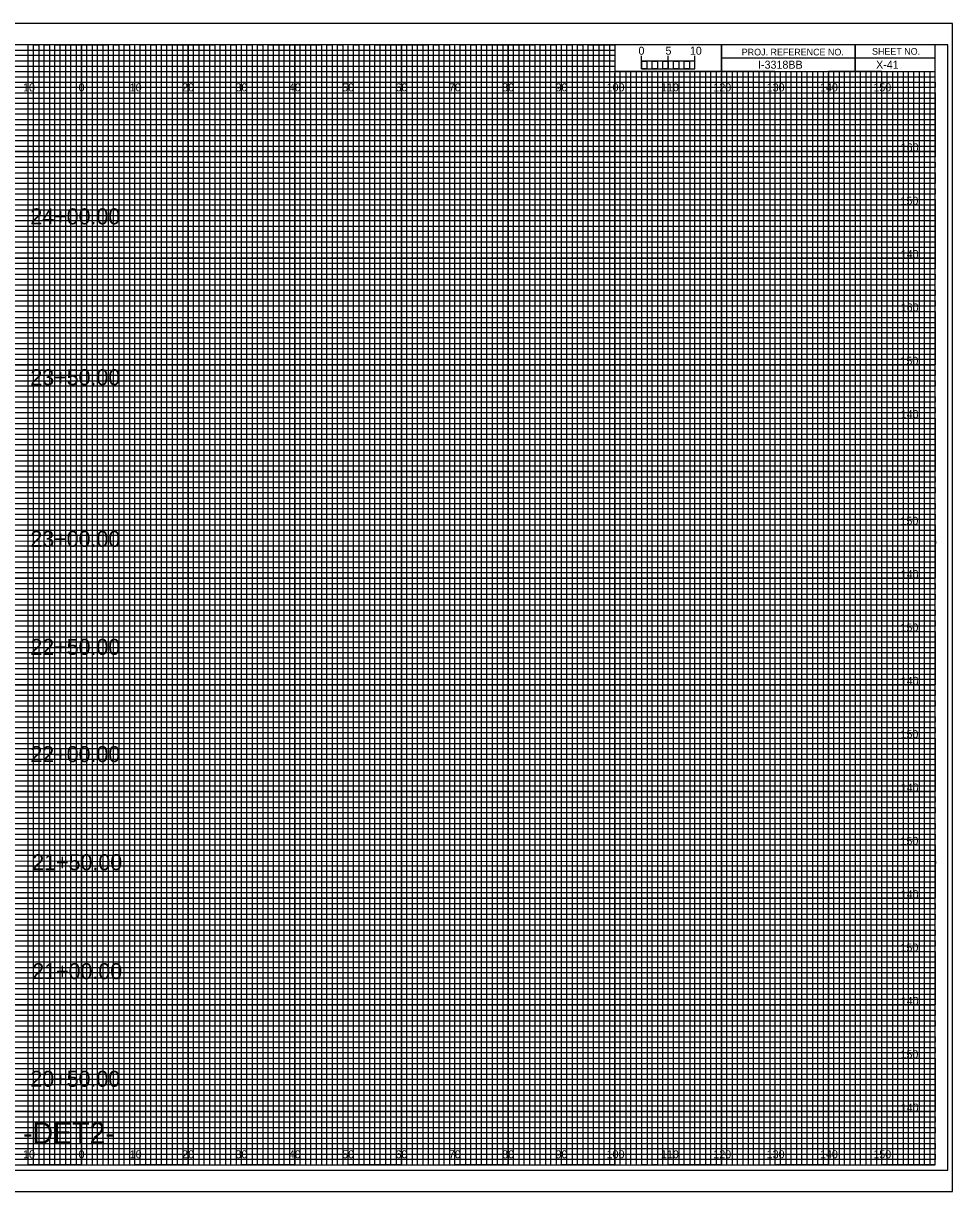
# Model space of a CAD drawing. Extents: x -13 to 323, y 215 to 434.
# Drawn here: x 149.1 to 323.3, y 215 to 434 of the extents above; entities that cross this region are included whole.
import ezdxf

# ---------------------------------------------------------------- set-up
doc = ezdxf.new("R2010")
doc.units = 0
for name, color, linetype in [('Exist Cross Section Cell', 7, 'Continuous'), ('Exist XS Center Line Elevation Label', 7, 'Continuous'), ('Exist XS Ground Line', 7, 'Continuous'), ('Prop CMT Guardrail Graphics', 7, 'Continuous'), ('Prop CMT Pvmt Course 1', 7, 'Continuous'), ('Prop CMT Pvmt Course 2', 7, 'Continuous'), ('Prop CMT Pvmt Course 3', 7, 'Continuous'), ('Prop CMT Pvmt Surface', 7, 'Continuous'), ('Prop CMT Pvmt Surface Shoulder', 7, 'Continuous'), ('Prop CMT Shld Paved Course 1', 7, 'Continuous'), ('Prop CMT Shld Paved Course 2', 7, 'Continuous'), ('Prop CMT Shld Paved Course 3', 7, 'Continuous'), ('Prop CMT Slope Grass', 7, 'Continuous'), ('Prop CMT Subgrade Earthwork', 7, 'Continuous'), ('Prop XS SE Text', 7, 'Continuous'), ('Prop XS Side Slope Text', 7, 'Continuous'), ('Scratch_Level_2', 7, 'Continuous')]:
    doc.layers.add(name, color=color, linetype=linetype)

msp = doc.modelspace()

# ---------------------------------------------------------------- linework, layer by layer
at = {"layer": 'Exist XS Center Line Elevation Label'}
for points in [[(145, 220), (155, 220), (155, 430), (165, 430), (165, 220), (175, 220), (175, 430), (185, 430), (185, 220), (195, 220), (195, 430), (205, 430), (205, 220), (215, 220), (215, 430), (225, 430), (225, 220), (235, 220), (235, 430), (245, 430), (245, 220), (255, 220), (255, 430), (259.93, 430), (260, 430), (260, 425), (264.99, 425), (264.99, 220), (275, 220), (275, 425), (285, 425), (285, 220), (295, 220), (295, 425), (305, 425), (305, 220), (315, 220), (315, 425)], [(0, 425), (275, 425)], [(0, 405), (320, 405), (320, 415), (0, 415)], [(0, 385), (320, 385), (320, 395), (0, 395)], [(0, 365), (320, 365), (320, 375), (0, 375)], [(0, 345), (320, 345), (320, 355), (0, 355)], [(0, 325), (320, 325), (320, 335), (0, 335)], [(0, 305), (320, 305), (320, 315), (0, 315)], [(0, 285), (320, 285), (320, 295), (0, 295)], [(0, 265), (320, 265), (320, 275), (0, 275)], [(0, 245), (320, 245), (320, 255), (0, 255)], [(0, 225), (320, 225), (320, 235), (0, 235)]]:
    msp.add_lwpolyline(points, dxfattribs=at)
at = {"layer": 'Exist XS Ground Line'}
for p, q in [((150, 430), (140, 430)), ((150, 220), (150, 430)), ((170, 430), (160, 430)), ((160, 430), (160, 220)), ((170, 220), (170, 430)), ((190, 430), (180, 430)), ((180, 430), (180, 220)), ((190, 220), (190, 430)), ((210, 430), (200, 430)), ((200, 430), (200, 220)), ((210, 220), (210, 430)), ((230, 430), (220, 430)), ((220, 430), (220, 220)), ((230, 220), (230, 430)), ((250, 430), (240, 430)), ((240, 430), (240, 220)), ((250, 220), (250, 430)), ((260, 430), (260, 220)), ((270, 220), (270, 425)), ((290, 425), (280, 425)), ((280, 425), (280, 220)), ((290, 220), (290, 425)), ((310, 425), (300, 425)), ((300, 425), (300, 220)), ((310, 220), (310, 425)), ((160, 220), (150, 220)), ((180, 220), (170, 220)), ((200, 220), (190, 220)), ((220, 220), (210, 220)), ((240, 220), (230, 220)), ((260, 220), (250, 220)), ((280, 220), (270, 220)), ((300, 220), (290, 220)), ((320, 220), (310, 220)), ((320, 220), (320, 220))]:
    msp.add_line(p, q, dxfattribs=at)
for points in [[(0, 420), (320, 420), (320, 410), (0, 410)], [(0, 400), (320, 400), (320, 390), (0, 390)], [(0, 380), (320, 380), (320, 370), (0, 370)], [(0, 360), (320, 360), (320, 350), (0, 350)], [(0, 340), (320, 340), (320, 330), (0, 330)], [(0, 320), (320, 320), (320, 310), (0, 310)], [(0, 300), (320, 300), (320, 290), (0, 290)], [(0, 280), (320, 280), (320, 270), (0, 270)], [(0, 260), (320, 260), (320, 250), (0, 250)], [(0, 240), (320, 240), (320, 230), (0, 230)]]:
    msp.add_lwpolyline(points, dxfattribs=at)
at = {"layer": 'Prop CMT Pvmt Course 1'}
for p, q in [((323.3, 434), (-13.4, 434)), ((-13.4, 215), (323.3, 215))]:
    msp.add_line(p, q, dxfattribs=at)
at = {"layer": 'Prop CMT Pvmt Surface'}
msp.add_lwpolyline([(-10.8, 219), (322.4, 219), (322.4, 430), (-10.8, 430)], close=True, dxfattribs=at)
at = {"layer": 'Prop CMT Pvmt Surface Shoulder'}
for p, q in [((150, 220), (150, 430)), ((160, 220), (160, 430)), ((170, 220), (170, 430)), ((180, 220), (180, 430)), ((190, 220), (190, 430)), ((200, 220), (200, 430)), ((210, 220), (210, 430)), ((220, 220), (220, 430)), ((230, 220), (230, 430)), ((240, 220), (240, 430)), ((250, 220), (250, 430)), ((260, 220), (260, 424.69)), ((270, 220), (270, 424.69)), ((280, 220), (280, 424.69)), ((290, 220), (290, 424.69)), ((300, 220), (300, 424.69)), ((310, 220), (310, 424.69)), ((0, 420), (320, 420)), ((0, 410), (320, 410)), ((0, 400), (320, 400)), ((0, 390), (320, 390)), ((0, 380), (320, 380)), ((0, 370), (320, 370)), ((0, 360), (320, 360)), ((0, 350), (320, 350)), ((0, 340), (320, 340)), ((0, 330), (320, 330)), ((0, 320), (320, 320)), ((0, 310), (320, 310)), ((0, 300), (320, 300)), ((0, 290), (320, 290)), ((0, 280), (320, 280)), ((0, 270), (320, 270)), ((0, 260), (320, 260)), ((0, 250), (320, 250)), ((0, 240), (320, 240)), ((0, 230), (320, 230))]:
    msp.add_line(p, q, dxfattribs=at)
at = {"layer": 'Prop CMT Shld Paved Course 1'}
for p, q in [((305, 430), (305, 425)), ((305, 425), (305, 430)), ((280, 427.5), (280, 425)), ((320, 427.49), (280, 427.49)), ((280, 425), (320, 425))]:
    msp.add_line(p, q, dxfattribs=at)
for points in [[(320, 430), (0, 430), (0, 220), (320, 220)], [(280, 430), (260, 430), (260, 425.03), (280, 425.03)], [(320, 430), (280, 430), (280, 425), (320, 425)]]:
    msp.add_lwpolyline(points, close=True, dxfattribs=at)
at = {"layer": 'Prop CMT Shld Paved Course 2'}
for p, q in [((267, 425), (266.01, 425)), ((266.01, 425), (266.01, 220)), ((267, 220), (267, 425)), ((269, 425), (268, 425)), ((268, 425), (268, 220)), ((269, 220), (269, 425)), ((266.01, 220), (265, 220)), ((268, 220), (267, 220))]:
    msp.add_line(p, q, dxfattribs=at)
for points in [[(150, 220), (151, 220), (151, 430), (152, 430), (152, 220)], [(152, 220), (153, 220), (153, 430), (154, 430), (154, 220)], [(155, 220), (156, 220), (156, 430), (157, 430), (157, 220)], [(157, 220), (158, 220), (158, 430), (159, 430), (159, 220)], [(160, 220), (161, 220), (161, 430), (162, 430), (162, 220)], [(162, 220), (163, 220), (163, 430), (164, 430), (164, 220)], [(165, 220), (166, 220), (166, 430), (167, 430), (167, 220)], [(167, 220), (168, 220), (168, 430), (169, 430), (169, 220)], [(170, 220), (171, 220), (171, 430), (172, 430), (172, 220)], [(172, 220), (173, 220), (173, 430), (174, 430), (174, 220)], [(175, 220), (176, 220), (176, 430), (177, 430), (177, 220)], [(177, 220), (178, 220), (178, 430), (179, 430), (179, 220)], [(180, 220), (181, 220), (181, 430), (182, 430), (182, 220)], [(182, 220), (183, 220), (183, 430), (184, 430), (184, 220)], [(185, 220), (186, 220), (186, 430), (187, 430), (187, 220)], [(187, 220), (188, 220), (188, 430), (189, 430), (189, 220)], [(190, 220), (191, 220), (191, 430), (192, 430), (192, 220)], [(192, 220), (193, 220), (193, 430), (194, 430), (194, 220)], [(195, 220), (196, 220), (196, 430), (197, 430), (197, 220)], [(197, 220), (198, 220), (198, 430), (199, 430), (199, 220)], [(200, 220), (201, 220), (201, 430), (202, 430), (202, 220)], [(202, 220), (203, 220), (203, 430), (204, 430), (204, 220)], [(205, 220), (206, 220), (206, 430), (207, 430), (207, 220)], [(207, 220), (208, 220), (208, 430), (209, 430), (209, 220)], [(210, 220), (211, 220), (211, 430), (212, 430), (212, 220)], [(212, 220), (213, 220), (213, 430), (214, 430), (214, 220)], [(215, 220), (216, 220), (216, 430), (217, 430), (217, 220)], [(217, 220), (218, 220), (218, 430), (219, 430), (219, 220)], [(220, 220), (221, 220), (221, 430), (222, 430), (222, 220)], [(222, 220), (223, 220), (223, 430), (224, 430), (224, 220)], [(225, 220), (226, 220), (226, 430), (227, 430), (227, 220)], [(227, 220), (228, 220), (228, 430), (229, 430), (229, 220)], [(230, 220), (231, 220), (231, 430), (232, 430), (232, 220)], [(232, 220), (233, 220), (233, 430), (234, 430), (234, 220)], [(235, 220), (236, 220), (236, 430), (237, 430), (237, 220)], [(237, 220), (238, 220), (238, 430), (239, 430), (239, 220)], [(240, 220), (241, 220), (241, 430), (242, 430), (242, 220)], [(242, 220), (243, 220), (243, 430), (244, 430), (244, 220)], [(245, 220), (246, 220), (246, 430), (247, 430), (247, 220)], [(247, 220), (248, 220), (248, 430), (249, 430), (249, 220)], [(250, 220), (251, 220), (251, 430), (252, 430), (252, 220)], [(252, 220), (253, 220), (253, 430), (254, 430), (254, 220)], [(255, 220), (256, 220), (256, 430), (257, 430), (257, 220)], [(257, 220), (258, 220), (258, 430), (259, 430), (259, 220)], [(260, 220), (261, 220), (261, 425), (262.02, 425), (262.02, 220)], [(262, 220), (263, 220), (263, 425), (263.99, 425), (263.99, 220)], [(270, 220), (270.98, 220), (270.98, 425), (272, 425), (272, 220)], [(272, 220), (273, 220), (273, 425), (274.05, 425), (274.05, 220)], [(275, 220), (276, 220), (276, 425), (277, 425), (277, 220)], [(277, 220), (278, 220), (278, 425), (279, 425), (279, 220)], [(280, 220), (281, 220), (281, 425), (282, 425), (282, 220)], [(282, 220), (283, 220), (283, 425), (284, 425), (284, 220)], [(285, 220), (286, 220), (286, 425), (287, 425), (287, 220)], [(287, 220), (288, 220), (288, 425), (289, 425), (289, 220)], [(290, 220), (291, 220), (291, 425), (292, 425), (292, 220)], [(292, 220), (293, 220), (293, 425), (294, 425), (294, 220)], [(295, 220), (296, 220), (296, 425), (297, 425), (297, 220)], [(297, 220), (298, 220), (298, 425), (299, 425), (299, 220)], [(300, 220), (301, 220), (301, 425), (302, 425), (302, 220)], [(302, 220), (303, 220), (303, 425), (304, 425), (304, 220)], [(305, 220), (306, 220), (306, 425), (307, 425), (307, 220)], [(307, 220), (308, 220), (308, 425), (309, 425), (309, 220)], [(310, 220), (311, 220), (311, 425), (312, 425), (312, 220)], [(312, 220), (313, 220), (313, 425), (314, 425), (314, 220)], [(315, 220), (316, 220), (316, 425), (317, 425), (317, 220)], [(317, 220), (318, 220), (318, 425), (319, 425), (319, 220)]]:
    msp.add_lwpolyline(points, dxfattribs=at)
at = {"layer": 'Prop CMT Shld Paved Course 3'}
for p, q in [((265, 425.49), (265, 427.9)), ((265, 426.9), (265, 427.9)), ((270, 425.49), (270, 427.9)), ((275, 425.49), (275, 427.9)), ((275, 426.9), (275, 427.9))]:
    msp.add_line(p, q, dxfattribs=at)
for points in [[(275, 426.9), (265, 426.9), (265, 425.49), (275, 425.49)], [(265, 426.9), (266, 426.9), (266, 425.49), (265, 425.49)], [(267, 426.9), (268, 426.9), (268, 425.49), (267, 425.49)], [(269, 426.9), (270, 426.9), (270, 425.49), (269, 425.49)], [(271, 426.9), (272, 426.9), (272, 425.49), (271, 425.49)], [(273, 426.9), (274, 426.9), (274, 425.49), (273, 425.49)]]:
    msp.add_lwpolyline(points, close=True, dxfattribs=at)
at = {"layer": 'Prop CMT Subgrade Earthwork'}
msp.add_lwpolyline([(-13.4, 215), (323.3, 215), (323.3, 434), (-13.4, 434)], close=True, dxfattribs=at)
at = {"layer": 'Scratch_Level_2'}
for p, q in [((0, 429), (260, 429)), ((260, 427.98), (0, 427.98)), ((260, 429), (260, 427.98)), ((0, 427), (260, 427)), ((260, 425.89), (0, 425.89)), ((260, 427), (260, 425.89)), ((0, 424), (320, 424))]:
    msp.add_line(p, q, dxfattribs=at)
for points in [[(0, 423), (270, 423), (320, 423), (320, 422), (0, 422)], [(0, 421), (320, 421), (320, 419), (0, 419)], [(0, 418), (320, 418), (320, 417), (0, 416.98)], [(0, 416), (320, 416), (320, 414), (0, 414)], [(0, 413), (320, 413), (320, 412), (0, 412)], [(0, 411), (320, 411), (320, 409), (0, 409)], [(0, 408), (320, 408), (320, 407), (0, 407)], [(0, 406), (320, 406), (320, 404), (0, 404)], [(0, 403), (320, 403), (320, 402), (0, 402)], [(0, 401), (320, 401), (320, 399), (0, 399)], [(0, 398), (320, 398), (320, 397), (0, 397)], [(0, 396), (320, 396), (320, 393.95), (320, 393), (320, 392), (0, 392)], [(0, 394), (320, 394), (320, 393), (0, 393)], [(0, 391), (320, 391), (320, 389), (0, 389.03)], [(0, 389.03), (320, 389), (320, 388), (0, 388)], [(0, 387), (320, 387), (320, 386), (0, 386)], [(0, 384), (320, 384), (320, 383), (0, 383)], [(0, 382), (320, 382), (320, 381), (0, 381)], [(-0.07, 378.89), (320, 378.89), (320, 377.88), (-0.07, 377.88)], [(0, 377), (320, 377), (320, 376), (0, 376)], [(0, 374), (320, 374), (320, 373), (0, 373)], [(0, 372), (320, 372), (320, 371), (0, 371)], [(0, 369), (320, 369), (320, 368), (0, 368)], [(0, 367), (320, 367), (320, 366), (0, 366)], [(0, 364), (320, 364), (320, 363), (0, 363)], [(0, 362), (320, 362), (320, 361), (0, 361)], [(0, 359), (320, 359), (319.99, 357.98), (0, 358)], [(0, 357), (320, 357), (320, 356), (0, 356)], [(0, 354), (320, 354), (320, 353), (0, 353)], [(0, 352), (320, 352), (320, 351), (0, 351)], [(0, 349), (320, 349), (320, 348), (0, 348)], [(0, 347), (320, 347), (320, 346), (0, 346)], [(0, 344), (320, 344), (320, 343), (0, 343)], [(0, 342), (320, 342), (320, 341), (0, 341)], [(0, 339), (320, 339), (320, 338), (0, 338)], [(0, 336.99), (320.07, 336.91), (320, 336), (0, 336)], [(0, 334), (320, 334), (320, 333), (0, 333)], [(0, 332), (320, 332), (320, 331), (0, 331)], [(0, 329), (320, 329), (320, 328), (0, 328)], [(0, 327), (320, 327), (320, 326), (0, 326)], [(0, 324), (320, 324), (320, 323), (0, 323)], [(0, 322), (320, 322), (320, 321), (0, 321)], [(0, 319), (320, 319), (320, 318), (0, 318)], [(0, 317), (320, 317), (320, 316), (0, 316)], [(0, 314), (320, 314), (320, 313), (0, 313)], [(0, 312), (320, 312), (320, 311), (0, 311)], [(0, 309), (320, 309), (320, 308), (0, 308)], [(0, 307), (320, 307), (320, 306), (0, 306)], [(0, 304), (320, 304), (320, 303), (0, 303)], [(0, 302), (320, 302), (320, 301), (0, 301)], [(0, 299), (320, 299), (319.99, 297.98), (0, 298)], [(0, 297), (320, 297), (320, 296), (0, 296)], [(0, 294), (320, 294), (320, 293), (0, 293)], [(0, 292), (320, 292), (320, 291), (0, 291)], [(0, 289), (320, 289), (320, 288), (0, 288)], [(0, 287), (320, 287), (320, 286), (0, 286)], [(0, 284), (320, 284), (320, 283), (0, 283)], [(0, 282), (320, 282), (320, 281), (0, 281)], [(0, 279), (320, 279), (320, 278), (0, 278)], [(0, 276.99), (320.07, 276.91), (320, 276), (0, 276)], [(0, 274), (320, 274), (320, 273), (0, 273)], [(0, 272), (320, 272), (320, 271), (0, 271)], [(0, 269), (320, 269), (320, 268), (0, 268)], [(0, 267), (320, 267), (320, 266), (0, 266)], [(0, 264), (320, 264), (320, 263), (0, 263)], [(0, 262), (320, 262), (320, 261), (0, 261)], [(0, 259), (320, 259), (320, 258), (0, 258)], [(0, 257), (320, 257), (320, 256), (0, 256)], [(0, 254), (320, 254), (320, 253), (0, 253)], [(0, 252), (320, 252), (320, 251), (0, 251)], [(0, 249), (320, 249), (320, 248), (0, 248)], [(0, 247), (320, 247), (320, 246), (0, 246)], [(0, 244), (320, 244), (320, 243), (0, 243)], [(0, 242), (320, 242), (320, 241), (0, 241)], [(0, 239), (320, 239), (320, 238), (0, 238)], [(0, 237), (320, 237), (320, 236), (0, 236)], [(0, 234), (320, 234), (320, 233), (0, 233)], [(0, 232), (320, 232), (320, 231), (0, 231)], [(0, 229), (320, 229), (320, 228), (0, 228)], [(0, 227), (320, 227), (320, 226), (0, 226)], [(0, 224), (320, 224), (320, 223), (0, 223)], [(0, 222), (320, 222), (320, 221), (0, 221)]]:
    msp.add_lwpolyline(points, dxfattribs=at)

# ---------------------------------------------------------------- texts
at = {"layer": 'Exist Cross Section Cell'}
for s, p in [('10', (149.04, 421.25)), ('0', (159.45, 421.25)), ('0', (159.45, 421.25)), ('10', (169.04, 421.25)), ('20', (178.86, 421.25)), ('30', (188.86, 421.25)), ('40', (198.86, 421.25)), ('50', (208.86, 421.25)), ('60', (218.86, 421.25)), ('70', (228.86, 421.25)), ('80', (238.86, 421.25)), ('90', (248.86, 421.25)), ('100', (258.44, 421.25)), ('110', (268.62, 421.25)), ('120', (278.44, 421.25)), ('130', (288.44, 421.25)), ('140', (298.44, 421.25)), ('150', (308.44, 421.25)), ('10', (149.04, 221.25)), ('0', (159.45, 221.25)), ('0', (159.45, 221.25)), ('10', (169.04, 221.25)), ('20', (178.86, 221.25)), ('30', (188.86, 221.25)), ('40', (198.86, 221.25)), ('50', (208.86, 221.25)), ('60', (218.86, 221.25)), ('70', (228.86, 221.25)), ('80', (238.86, 221.25)), ('90', (248.86, 221.25)), ('100', (258.44, 221.25)), ('110', (268.62, 221.25)), ('120', (278.44, 221.25)), ('130', (288.44, 221.25)), ('140', (298.44, 221.25)), ('150', (308.44, 221.25))]:
    msp.add_text(s, height=1.5, dxfattribs=at).set_placement(p)
at = {"layer": 'Prop CMT Guardrail Graphics'}
for s, p in [('5', (269.47, 428.12)), ('10', (274.04, 428.12))]:
    msp.add_text(s, height=1.5, dxfattribs=at).set_placement(p)
at = {"layer": 'Prop CMT Pvmt Course 2'}
msp.add_text('X-41', height=1.5, dxfattribs=at).set_placement((308.95, 425.5))
at = {"layer": 'Prop CMT Pvmt Course 3'}
for s, p in [('160', (313.57, 410)), ('150', (313.52, 400)), ('140', (313.57, 390)), ('160', (313.57, 380)), ('150', (313.52, 370)), ('140', (313.57, 360)), ('150', (313.52, 340)), ('140', (313.57, 330)), ('150', (313.52, 320)), ('140', (313.57, 310)), ('150', (313.52, 300)), ('140', (313.57, 290)), ('150', (313.52, 280)), ('140', (313.57, 270)), ('150', (313.52, 260)), ('140', (313.57, 250)), ('150', (313.52, 240)), ('140', (313.57, 230))]:
    msp.add_text(s, height=1.5, dxfattribs=at).set_placement(p)
at = {"layer": 'Prop CMT Shld Paved Course 1'}
for s, p in [('PROJ. REFERENCE NO.', (283.77, 427.99)), ('SHEET NO.', (308.19, 428.12))]:
    msp.add_text(s, height=1.25, dxfattribs=at).set_placement(p)
at = {"layer": 'Prop CMT Shld Paved Course 3'}
msp.add_text('0', height=1.5, dxfattribs=at).set_placement((264.41, 428.12))
at = {"layer": 'Prop CMT Slope Grass'}
for s, p in [('24+00.00', (150.41, 396.32)), ('23+50.00', (150.41, 366.16)), ('23+00.00', (150.41, 335.86)), ('22+50.00', (150.41, 315.62)), ('22+00.00', (150.41, 295.52)), ('21+50.00', (150.77, 275.25)), ('21+00.00', (150.77, 254.83)), ('20+50.00', (150.41, 234.66))]:
    msp.add_text(s, height=3, dxfattribs=at).set_placement(p)
at = {"layer": 'Prop XS SE Text'}
msp.add_text('-DET2-', height=4, dxfattribs=at).set_placement((149.02, 224))
at = {"layer": 'Prop XS Side Slope Text'}
msp.add_text('I-3318BB', height=1.5, dxfattribs=at).set_placement((286.82, 425.5))

doc.saveas('drawing.dxf')
